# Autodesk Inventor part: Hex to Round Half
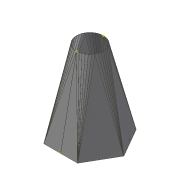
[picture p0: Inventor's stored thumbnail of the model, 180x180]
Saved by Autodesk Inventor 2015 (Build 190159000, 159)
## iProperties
Created: 2013-06
Part Number: Hex to Round Half
Material: Steel, Mild
Document SubType Name: Sheet Metal
Designer: 1103005
Density: 1 g/cm^3
Flat Pattern Width: 51.4551 cm
Flat Pattern Length: 53.854 cm
Flat Pattern Area: 2771.06 cm^2
Sheet Metal Rule: Default_mm
Sheet Metal Width: 514.551 mm
Sheet Metal Length: 538.540 mm
Sheet Metal Area: 277106.382 mm^2
Appearance: Steel
Author: 1103005
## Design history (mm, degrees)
sketch "Sketch1"
  geometry: L1 (-187.639, 0)-(187.639, 0); L2 (187.639, 0)-(93.819, -162.5); L3 (93.819, -162.5)-(-93.819, -162.5); L4 (-93.819, -162.5)-(-187.639, 0); L5 (-93.819, -162.5)-(-187.639, 0); L6 (-187.639, 0)-(-93.819, 162.5); L7 (-93.819, 162.5)-(93.819, 162.5); L8 (93.819, 162.5)-(187.639, 0); L9 (187.639, 0)-(93.819, -162.5); L10 (93.819, -162.5)-(-93.819, -162.5); 6 further points
  constraints: 20 end point, 4 coincident, 2 midpoint, 1 horizontal, 1 vertical alignment, 19 other
  dimensions: "d26" = 162.5 distance between parallel lines of L1 L3
workplane "Work Plane1"
node "Lofted Flange1"
  sketch "Sketch2"
    geometry: L1 (74, 0)-(-74, 0); A1 r 74 centre (0, 0) between (-74, 0) and (74, 0); 1 further point
    constraints: 2 end point, 2 point on circle, 1 centre point, 1 coincident, 1 horizontal, 1 midpoint
    dimensions: "d2" = 148 diameter of A1
workpoint "Work Point1"
workpoint "Work Point2"
feature "Rip1" dims "d40" = 0.5
workpoint "Work Point3"
workpoint "Work Point4"
mirror "Mirror1"
sketch "Sketch10"
  geometry: L1 (467.982, 0)-(430.911, 182.545) reference; L2 (449.447, 91.273)-(434.747, 88.287); 2 further points
  constraints: 2 end point, 1 coincident, 1 midpoint, 1 perpendicular
  dimensions: "d55" = 15 distance of L2.start L2.end
hole "Hole2" sketch "Sketch10" at (434.747, 88.287) diameter "d56" = 5; stored, may be unused: countersink angle "d60" = 90 deg, drill point angle "d62" = 118 deg; dims "d57" = 6, "d58" = 4, "d59" = 2, "d61" = 1.2 (= Thickness)
pattern_circular "Circular Pattern2" dims angle "d64" = 360 deg
body "Solid1"
bend "Bend1" dims "d4" = 1.2 (= BendRadius), "d5" = 1.2 (= BendReliefWidth), "d6" = 0.6 (= BendReliefDepth), "d7" = 2.4 (= MinimumRemnant), "d8" = 1.2 (= BendRadius), "SeamGap" = 0.01, "Thickness" = 1.2
feature "Definition1" dims "d40" = 0.5
other parameters: "BendRadius" = 1.2 (= Thickness), "BendReliefWidth" = 1.2 (= Thickness), "BendReliefDepth" = 0.6 (= 0.5 x Thickness), "CornerReliefSize" = 4.8 (= 4 x Thickness), "MinimumRemnant" = 2.4 (= 2 x Thickness), "TransitionRadius" = 1.2 (= BendRadius), "JacobiRadiusSize" = 1.2 (= BendRadius), "GapSize" = 1.2 (= Thickness), "d3" = 0.5, "d54" = 5 deg, "BendRadius" = 1.2, "BendReliefDepth" = 0.6, "BendReliefWidth" = 1.2, "CornerReliefSize" = 4.8, "GapSize" = 1.2, "JacobiRadiusSize" = 1.2, "MinimumRemnant" = 2.4, "Thickness" = 1.2, "TransitionRadius" = 1.2
